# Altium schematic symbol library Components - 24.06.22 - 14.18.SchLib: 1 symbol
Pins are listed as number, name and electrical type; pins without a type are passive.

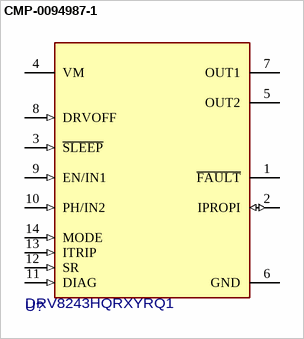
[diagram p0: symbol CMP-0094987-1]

## CMP-0094987-1
designator U?, comment DRV8243HQRXYRQ1
Automotive 40-V, 12-A H-Bridge driver with integrated current sensing and feedback 14-VQFN-HR -40 to 125; Manufacturer: Texas Instruments; Motor Type: Brushed; SizeZ_mm: 1mm; AEC Grade: Grade 1; Number Of Outputs: 2; Switching Frequency: 25kHz; Standoff Height: 0mm; TaMin_C: -40°C; AEC Qualified: Yes; Max Supply Voltage: 35V; Min Supply Voltage: 4.5V; TJmax_C: +150°C; TaMax_C: +125°C
footprint RXY0014A-MFG
pins: 1 ~{FAULT} (oc), 2 IPROPI (io), 3 ~{SLEEP} (in), 4 VM (power), 5 OUT2, 6 GND (power), 7 OUT1, 8 DRVOFF (in), 9 EN/IN1 (in), 10 PH/IN2 (in), 11 DIAG (in), 12 SR (in), 13 ITRIP (in), 14 MODE (in)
